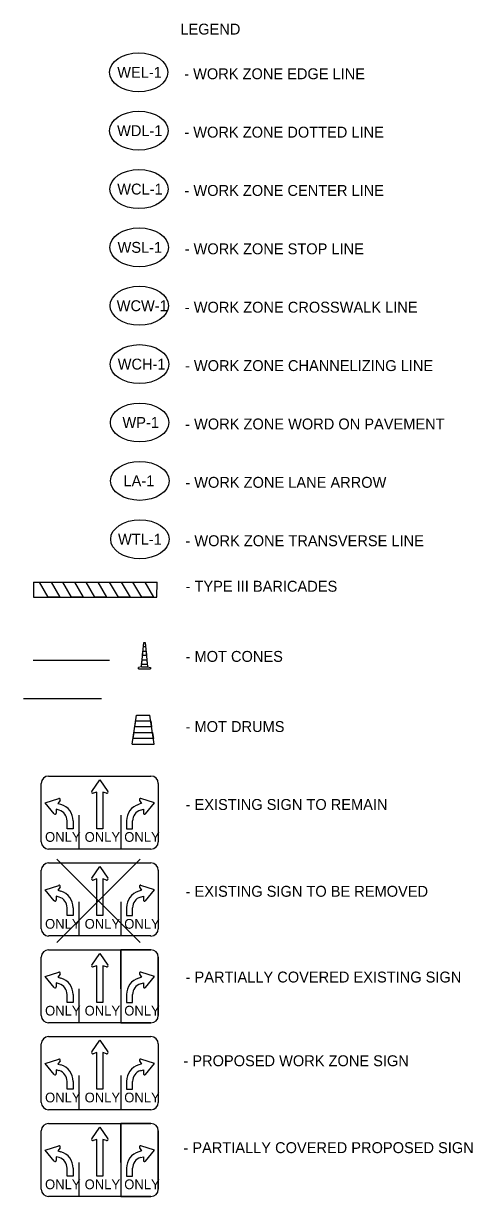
# Model space of a CAD drawing. Extents: x -12.2 to 34.1, y -24.5 to 43.2.
# Drawn here: x 17.37 to 23.13, y 28.11 to 43.16 of the extents above; entities that cross this region are included whole.
import ezdxf

# ---------------------------------------------------------------- set-up
doc = ezdxf.new("R2010")
doc.units = 0
for name, color, linetype in [('MT_P_Drums', 7, 'Continuous'), ('MT_P_Work_Area', 7, 'Continuous'), ('SH_Text', 7, 'Continuous'), ('SN_P_Signs', 7, 'Continuous'), ('SN_X_Public', 7, 'Continuous'), ('VG_P_Cells', 7, 'Continuous')]:
    doc.layers.add(name, color=color, linetype=linetype)

msp = doc.modelspace()

# ---------------------------------------------------------------- linework, layer by layer
at = {"layer": 'MT_P_Drums'}
for p, q in [((18.884, 34.902), (18.914, 35.217)), ((18.933, 35.217), (18.963, 34.902)), ((18.475, 34.987), (17.494, 34.987)), ((18.884, 34.902), (18.846, 34.897)), ((18.846, 34.879), (18.846, 34.897)), ((18.846, 34.879), (19.001, 34.879)), ((18.884, 34.902), (18.963, 34.902)), ((18.884, 34.879), (18.963, 34.879)), ((18.963, 34.902), (19.001, 34.897)), ((19.001, 34.897), (19.001, 34.879)), ((18.372, 34.495), (17.371, 34.495)), ((18.767, 33.911), (18.823, 34.286)), ((18.823, 34.286), (18.992, 34.286)), ((19.048, 33.911), (18.992, 34.286)), ((18.767, 33.911), (19.048, 33.911))]:
    msp.add_line(p, q, dxfattribs=at)
for points in [[(18.898, 35.048), (18.903, 35.104), (18.944, 35.104), (18.949, 35.048)], [(18.909, 35.16), (18.914, 35.217), (18.933, 35.217), (18.938, 35.16)], [(18.887, 34.935), (18.892, 34.992), (18.955, 34.992), (18.96, 34.935)], [(18.801, 34.136), (18.812, 34.211), (19.003, 34.211), (19.014, 34.136)], [(18.778, 33.986), (18.789, 34.061), (19.026, 34.061), (19.037, 33.986)]]:
    msp.add_lwpolyline(points, close=True, dxfattribs=at)
at = {"layer": 'MT_P_Work_Area'}
for p, q in [((17.499, 35.992), (19.085, 35.992)), ((17.499, 35.992), (17.499, 35.797)), ((19.082, 35.797), (19.085, 35.992)), ((17.499, 35.797), (19.082, 35.797))]:
    msp.add_line(p, q, dxfattribs=at)
for points in [[(17.575, 35.992), (17.725, 35.992), (17.837, 35.797), (17.687, 35.797)], [(17.875, 35.992), (18.025, 35.992), (18.138, 35.797), (17.987, 35.797)], [(18.175, 35.992), (18.325, 35.992), (18.438, 35.797), (18.288, 35.797)], [(18.475, 35.992), (18.625, 35.992), (18.738, 35.797), (18.588, 35.797)], [(18.926, 35.992), (19.038, 35.797), (18.888, 35.797), (18.776, 35.992)]]:
    msp.add_lwpolyline(points, close=True, dxfattribs=at)
at = {"layer": 'SH_Text'}
for centre in [(18.849, 42.532), (18.851, 41.783), (18.853, 41.034), (18.855, 40.286), (18.857, 39.537), (18.859, 38.788), (18.861, 38.039), (18.863, 37.29), (18.865, 36.541)]:
    msp.add_ellipse(centre, major_axis=(0.375, 0), ratio=0.666667, dxfattribs=at)
at = {"layer": 'SN_P_Signs'}
for p, q in [((18.248, 29.964), (18.35, 30.113)), ((18.35, 30.113), (18.453, 29.964)), ((18.311, 29.954), (18.265, 29.94)), ((18.311, 29.484), (18.311, 29.954)), ((18.436, 29.94), (18.389, 29.954)), ((18.389, 29.954), (18.389, 29.484)), ((17.65, 29.817), (17.823, 29.872)), ((17.764, 29.675), (17.65, 29.817)), ((17.84, 29.848), (17.813, 29.808)), ((17.813, 29.808), (17.851, 29.797)), ((18.887, 29.808), (18.849, 29.797)), ((18.86, 29.848), (18.887, 29.808)), ((19.051, 29.817), (18.878, 29.872)), ((18.937, 29.675), (19.051, 29.817)), ((17.829, 29.722), (17.791, 29.733)), ((17.791, 29.733), (17.791, 29.685)), ((18.08, 29.66), (18.08, 29.222)), ((18.621, 29.66), (18.621, 29.222)), ((18.872, 29.722), (18.91, 29.733)), ((18.91, 29.733), (18.909, 29.685)), ((17.93, 29.484), (17.93, 29.586)), ((18.009, 29.586), (18.009, 29.484)), ((18.692, 29.586), (18.692, 29.484)), ((18.77, 29.484), (18.77, 29.586)), ((18.009, 29.484), (17.93, 29.484)), ((18.389, 29.484), (18.311, 29.484)), ((18.692, 29.484), (18.77, 29.484)), ((18.248, 28.849), (18.35, 28.999)), ((18.35, 28.999), (18.453, 28.849)), ((17.65, 28.702), (17.823, 28.758)), ((18.311, 28.84), (18.265, 28.825)), ((18.311, 28.37), (18.311, 28.84)), ((18.436, 28.825), (18.389, 28.84)), ((18.389, 28.84), (18.389, 28.37)), ((19.051, 28.702), (18.878, 28.758)), ((17.764, 28.561), (17.65, 28.702)), ((17.829, 28.608), (17.791, 28.619)), ((17.791, 28.619), (17.791, 28.571)), ((17.84, 28.734), (17.813, 28.694)), ((17.813, 28.694), (17.851, 28.683)), ((18.887, 28.694), (18.849, 28.683)), ((18.86, 28.734), (18.887, 28.694)), ((18.872, 28.608), (18.91, 28.619)), ((18.91, 28.619), (18.909, 28.571)), ((18.937, 28.561), (19.051, 28.702)), ((17.93, 28.37), (17.93, 28.471)), ((18.009, 28.471), (18.009, 28.37)), ((18.08, 28.545), (18.08, 28.108)), ((18.621, 28.545), (18.621, 28.108)), ((18.692, 28.471), (18.692, 28.37)), ((18.77, 28.37), (18.77, 28.471)), ((18.009, 28.37), (17.93, 28.37)), ((18.389, 28.37), (18.311, 28.37)), ((18.692, 28.37), (18.77, 28.37))]:
    msp.add_line(p, q, dxfattribs=at)
for points in [[(17.694, 30.16), (19.007, 30.16)], [(17.6, 29.316), (17.6, 30.066)], [(19.1, 30.066), (19.1, 29.316)], [(19.007, 29.222), (17.694, 29.222)], [(17.6, 28.202), (17.6, 28.952)], [(17.694, 29.045), (19.007, 29.045)], [(19.1, 28.952), (19.1, 28.202)], [(19.007, 28.108), (17.694, 28.108)]]:
    msp.add_lwpolyline(points, dxfattribs=at)
for centre, radius, start, end in [((17.694, 30.066), 0.0938, 90, 180), ((19.007, 30.066), 0.0938, 0, 90), ((18.261, 29.955), 0.0156, 145.4837, 287.3618), ((18.44, 29.955), 0.0156, 252.6382, 34.5163), ((17.828, 29.857), 0.0156, 325.9114, 107.7895), ((18.873, 29.857), 0.0156, 72.2105, 214.0886), ((17.776, 29.685), 0.0156, 218.7569, 0.635), ((17.788, 29.586), 0.143, 0, 73.2732), ((17.788, 29.586), 0.221, 0, 73.2732), ((18.913, 29.586), 0.221, 106.7268, 180), ((18.913, 29.586), 0.143, 106.7268, 180), ((18.925, 29.685), 0.0156, 179.365, 321.2431), ((17.694, 29.316), 0.0938, 180, 270), ((19.007, 29.316), 0.0938, 270, 0), ((17.694, 28.952), 0.0938, 90, 180), ((19.007, 28.952), 0.0938, 0, 90), ((17.828, 28.743), 0.0156, 325.9114, 107.7895), ((18.261, 28.84), 0.0156, 145.4837, 287.3618), ((18.44, 28.84), 0.0156, 252.6382, 34.5163), ((18.873, 28.743), 0.0156, 72.2105, 214.0886), ((17.788, 28.471), 0.143, 0, 73.2732), ((17.788, 28.471), 0.221, 0, 73.2732), ((18.913, 28.471), 0.221, 106.7268, 180), ((18.913, 28.471), 0.143, 106.7268, 180), ((17.776, 28.571), 0.0156, 218.7569, 0.635), ((18.925, 28.571), 0.0156, 179.365, 321.2431), ((17.694, 28.202), 0.0938, 180, 270), ((19.007, 28.202), 0.0938, 270, 0)]:
    msp.add_arc(centre, radius, start, end, dxfattribs=at)
at = {"layer": 'SN_X_Public'}
for p, q in [((18.248, 33.306), (18.35, 33.456)), ((18.35, 33.456), (18.453, 33.306)), ((18.311, 33.297), (18.265, 33.282)), ((18.311, 32.827), (18.311, 33.297)), ((18.436, 33.282), (18.389, 33.297)), ((18.389, 33.297), (18.389, 32.827)), ((17.65, 33.159), (17.823, 33.215)), ((17.764, 33.018), (17.65, 33.159)), ((17.84, 33.191), (17.813, 33.151)), ((17.813, 33.151), (17.851, 33.14)), ((18.887, 33.151), (18.849, 33.14)), ((18.86, 33.191), (18.887, 33.151)), ((19.051, 33.159), (18.878, 33.215)), ((18.937, 33.018), (19.051, 33.159)), ((17.829, 33.065), (17.791, 33.076)), ((17.791, 33.076), (17.791, 33.028)), ((18.08, 33.003), (18.08, 32.565)), ((18.621, 33.003), (18.621, 32.565)), ((18.872, 33.065), (18.91, 33.076)), ((18.91, 33.076), (18.909, 33.028)), ((17.93, 32.827), (17.93, 32.928)), ((18.009, 32.827), (17.93, 32.827)), ((18.009, 32.928), (18.009, 32.827)), ((18.389, 32.827), (18.311, 32.827)), ((18.692, 32.928), (18.692, 32.827)), ((18.692, 32.827), (18.77, 32.827)), ((18.77, 32.827), (18.77, 32.928)), ((18.248, 32.192), (18.35, 32.341)), ((18.35, 32.341), (18.453, 32.192)), ((17.65, 32.045), (17.823, 32.1)), ((17.84, 32.077), (17.813, 32.037)), ((18.311, 32.183), (18.265, 32.168)), ((18.311, 31.712), (18.311, 32.183)), ((18.436, 32.168), (18.389, 32.183)), ((18.389, 32.183), (18.389, 31.712)), ((18.86, 32.077), (18.887, 32.037)), ((19.051, 32.045), (18.878, 32.1)), ((17.764, 31.904), (17.65, 32.045)), ((17.829, 31.951), (17.791, 31.962)), ((17.791, 31.962), (17.791, 31.914)), ((17.813, 32.037), (17.851, 32.025)), ((18.887, 32.037), (18.849, 32.025)), ((18.872, 31.951), (18.91, 31.962)), ((18.91, 31.962), (18.909, 31.914)), ((18.937, 31.904), (19.051, 32.045)), ((17.93, 31.712), (17.93, 31.814)), ((18.009, 31.814), (18.009, 31.712)), ((18.08, 31.888), (18.08, 31.451)), ((18.621, 31.888), (18.621, 31.451)), ((18.692, 31.814), (18.692, 31.712)), ((18.77, 31.712), (18.77, 31.814)), ((18.009, 31.712), (17.93, 31.712)), ((18.389, 31.712), (18.311, 31.712)), ((18.692, 31.712), (18.77, 31.712)), ((18.248, 31.078), (18.35, 31.227)), ((18.35, 31.227), (18.453, 31.078)), ((18.621, 30.774), (18.621, 31.274)), ((19.007, 31.274), (18.621, 31.274)), ((18.621, 31.274), (18.621, 30.774)), ((19.1, 30.43), (19.1, 31.18)), ((18.311, 31.068), (18.265, 31.054)), ((18.311, 30.598), (18.311, 31.068)), ((18.436, 31.054), (18.389, 31.068)), ((18.389, 31.068), (18.389, 30.598)), ((17.65, 30.931), (17.823, 30.986)), ((17.764, 30.789), (17.65, 30.931)), ((17.84, 30.963), (17.813, 30.923)), ((17.813, 30.923), (17.851, 30.911)), ((18.887, 30.923), (18.849, 30.911)), ((18.86, 30.963), (18.887, 30.923)), ((19.051, 30.931), (18.878, 30.986)), ((18.937, 30.789), (19.051, 30.931)), ((17.829, 30.836), (17.791, 30.848)), ((17.791, 30.848), (17.791, 30.799)), ((18.08, 30.774), (18.08, 30.336)), ((18.621, 30.774), (18.621, 30.336)), ((18.621, 30.774), (18.621, 30.336)), ((18.872, 30.836), (18.91, 30.848)), ((18.91, 30.848), (18.909, 30.799)), ((17.93, 30.598), (17.93, 30.7)), ((18.009, 30.598), (17.93, 30.598)), ((18.009, 30.7), (18.009, 30.598)), ((18.389, 30.598), (18.311, 30.598)), ((18.692, 30.7), (18.692, 30.598)), ((18.692, 30.598), (18.77, 30.598)), ((18.77, 30.598), (18.77, 30.7)), ((18.621, 30.336), (19.007, 30.336)), ((18.621, 28.545), (18.621, 29.045)), ((19.007, 29.045), (18.621, 29.045)), ((18.621, 29.045), (18.621, 28.545)), ((19.1, 28.202), (19.1, 28.952)), ((18.621, 28.545), (18.621, 28.108)), ((18.621, 28.108), (19.007, 28.108))]:
    msp.add_line(p, q, dxfattribs=at)
for points in [[(17.694, 33.503), (19.007, 33.503)], [(17.6, 32.659), (17.6, 33.409)], [(19.1, 33.409), (19.1, 32.659)], [(19.007, 32.565), (17.694, 32.565)], [(17.694, 32.388), (19.007, 32.388)], [(17.6, 31.544), (17.6, 32.294)], [(19.1, 32.294), (19.1, 31.544)], [(19.007, 31.451), (17.694, 31.451)], [(17.6, 30.43), (17.6, 31.18)], [(17.694, 31.274), (19.007, 31.274)], [(19.1, 31.18), (19.1, 30.43)], [(19.007, 30.336), (17.694, 30.336)]]:
    msp.add_lwpolyline(points, dxfattribs=at)
for centre, radius, start, end in [((17.694, 33.409), 0.0938, 90, 180), ((19.007, 33.409), 0.0938, 0, 90), ((18.261, 33.297), 0.0156, 145.4837, 287.3618), ((18.44, 33.297), 0.0156, 252.6382, 34.5163), ((17.828, 33.2), 0.0156, 325.9114, 107.7895), ((17.788, 32.928), 0.221, 0, 73.2732), ((18.913, 32.928), 0.221, 106.7268, 180), ((18.873, 33.2), 0.0156, 72.2105, 214.0886), ((17.776, 33.028), 0.0156, 218.7569, 0.635), ((17.788, 32.928), 0.143, 0, 73.2732), ((18.913, 32.928), 0.143, 106.7268, 180), ((18.925, 33.028), 0.0156, 179.365, 321.2431), ((17.694, 32.659), 0.0938, 180, 270), ((19.007, 32.659), 0.0938, 270, 0), ((17.694, 32.294), 0.0938, 90, 180), ((19.007, 32.294), 0.0938, 0, 90), ((17.828, 32.086), 0.0156, 325.9114, 107.7895), ((18.261, 32.183), 0.0156, 145.4837, 287.3618), ((18.44, 32.183), 0.0156, 252.6382, 34.5163), ((18.873, 32.086), 0.0156, 72.2105, 214.0886), ((17.776, 31.914), 0.0156, 218.7569, 0.635), ((17.788, 31.814), 0.143, 0, 73.2732), ((17.788, 31.814), 0.221, 0, 73.2732), ((18.913, 31.814), 0.221, 106.7268, 180), ((18.913, 31.814), 0.143, 106.7268, 180), ((18.925, 31.914), 0.0156, 179.365, 321.2431), ((17.694, 31.544), 0.0938, 180, 270), ((19.007, 31.544), 0.0938, 270, 0), ((17.694, 31.18), 0.0938, 90, 180), ((19.007, 31.18), 0.0938, 0, 90), ((19.007, 31.18), 0.0938, 0, 90), ((18.261, 31.069), 0.0156, 145.4837, 287.3618), ((18.44, 31.069), 0.0156, 252.6382, 34.5163), ((17.828, 30.971), 0.0156, 325.9114, 107.7895), ((17.788, 30.7), 0.221, 0, 73.2732), ((18.913, 30.7), 0.221, 106.7268, 180), ((18.873, 30.971), 0.0156, 72.2105, 214.0886), ((17.776, 30.799), 0.0156, 218.7569, 0.635), ((17.788, 30.7), 0.143, 0, 73.2732), ((18.913, 30.7), 0.143, 106.7268, 180), ((18.925, 30.799), 0.0156, 179.365, 321.2431), ((17.694, 30.43), 0.0938, 180, 270), ((19.007, 30.43), 0.0938, 270, 0), ((19.007, 30.43), 0.0938, 270, 0), ((19.007, 28.952), 0.0938, 0, 90), ((19.007, 28.202), 0.0938, 270, 0)]:
    msp.add_arc(centre, radius, start, end, dxfattribs=at)
at = {"layer": 'VG_P_Cells'}
for p, q in [((17.798, 32.435), (18.867, 31.366)), ((18.867, 32.435), (17.798, 31.366)), ((18.332, 31.901), (18.332, 31.901))]:
    msp.add_line(p, q, dxfattribs=at)

# ---------------------------------------------------------------- texts
at = {"layer": 'SH_Text'}
for s, p in [('LEGEND', (19.384, 43.016)), ('WEL-1', (18.574, 42.462)), ('- WORK ZONE EDGE LINE', (19.433, 42.443)), ('WDL-1', (18.572, 41.713)), ('- WORK ZONE DOTTED LINE', (19.435, 41.694)), ('WCL-1', (18.574, 40.964)), ('- WORK ZONE CENTER LINE', (19.437, 40.946)), ('WSL-1', (18.578, 40.216)), ('- WORK ZONE STOP LINE', (19.439, 40.197)), ('WCW-1', (18.567, 39.467)), ('- WORK ZONE CROSSWALK LINE', (19.441, 39.448)), ('WCH-1', (18.58, 38.718)), ('- WORK ZONE CHANNELIZING LINE', (19.443, 38.699)), ('WP-1', (18.641, 37.969)), ('- WORK ZONE WORD ON PAVEMENT', (19.445, 37.95)), ('LA-1', (18.654, 37.22)), ('- WORK ZONE LANE ARROW', (19.447, 37.201)), ('WTL-1', (18.584, 36.471)), ('- WORK ZONE TRANSVERSE LINE', (19.449, 36.452)), ('- TYPE III BARICADES', (19.451, 35.868)), ('- MOT CONES', (19.451, 34.968)), ('- MOT DRUMS', (19.451, 34.068)), ('- EXISTING SIGN TO REMAIN', (19.451, 33.068)), ('- EXISTING SIGN TO BE REMOVED', (19.451, 31.954)), ('- PARTIALLY COVERED EXISTING SIGN', (19.451, 30.854)), ('- PROPOSED WORK ZONE SIGN', (19.423, 29.78)), ('- PARTIALLY COVERED PROPOSED SIGN', (19.423, 28.665))]:
    msp.add_text(s, height=0.14, dxfattribs=at).set_placement(p)
at = {"layer": 'SN_P_Signs'}
for p in [(17.648, 29.316), (18.156, 29.316), (18.664, 29.316), (17.648, 28.202), (18.156, 28.202), (18.664, 28.202)]:
    msp.add_text('ONLY', height=0.125, dxfattribs=at).set_placement(p)
at = {"layer": 'SN_X_Public'}
for p in [(17.648, 32.659), (18.156, 32.659), (18.664, 32.659), (17.648, 31.544), (18.156, 31.544), (18.664, 31.544), (17.648, 30.43), (18.156, 30.43), (18.664, 30.43)]:
    msp.add_text('ONLY', height=0.125, dxfattribs=at).set_placement(p)

doc.saveas('drawing.dxf')
